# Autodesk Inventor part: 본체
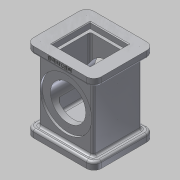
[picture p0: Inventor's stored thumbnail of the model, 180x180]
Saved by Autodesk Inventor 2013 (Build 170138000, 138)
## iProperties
Created: 2017-08
Part Number: 본체
Material: 알루미늄 6061
Document SubType Name: 모델링
Designer: Administrator
Density: 1 g/cm^3
Author: Administrator
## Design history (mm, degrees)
sketch "스케치5"
  geometry: L1 (-939.8, -838.2)-(939.8, -838.2); L2 (939.8, -838.2)-(939.8, 838.2); L3 (939.8, 838.2)-(-939.8, 838.2); L4 (-939.8, 838.2)-(-939.8, -838.2); L5 (-939.8, -838.2)-(939.8, 838.2); L6 (939.8, -838.2)-(-939.8, 838.2); 1 further point
  constraints: 12 end point, 2 midpoint, 2 parallel, 1 horizontal, 1 perpendicular
  dimensions: "d6" = 1879.6 distance of L2.end L3.end; "d8" = 1676.4 distance of L3.end L1.start
extrude "돌출1" new body sketch "스케치5" distance "d9" = 2743.2; taper "d10" = 0 deg
sketch "스케치8"
  geometry: L1 (939.8, -838.2)-(-939.8, -838.2) reference; L2 (939.8, 838.2)-(939.8, -838.2) reference; L3 (-939.8, 838.2)-(939.8, 838.2) reference; L4 (-939.8, -838.2)-(-939.8, 838.2) reference; L5 (-1168.4, -1041.4)-(1168.4, -1041.4); L6 (1168.4, -1041.4)-(1168.4, 1041.4); L7 (1168.4, 1041.4)-(-1168.4, 1041.4); L8 (-1168.4, 1041.4)-(-1168.4, -1041.4); L9 (-1168.4, -1041.4)-(1168.4, 1041.4); L10 (1168.4, -1041.4)-(-1168.4, 1041.4); 1 further point
  constraints: 12 end point, 2 midpoint, 2 parallel, 1 horizontal, 1 perpendicular
  dimensions: "d19" = 2336.8 distance of L6.end L7.end; "d21" = 2082.8 distance of L7.end L5.start
extrude "돌출3" join sketch "스케치8" distance "d22" = 254; taper "d23" = 0 deg
sketch "스케치9"
  geometry: L1 (-609.6, -609.6)-(609.6, -609.6); L2 (609.6, -609.6)-(609.6, 609.6); L3 (609.6, 609.6)-(-609.6, 609.6); L4 (-609.6, 609.6)-(-609.6, -609.6); L5 (-609.6, -609.6)-(609.6, 609.6); L6 (609.6, -609.6)-(-609.6, 609.6); 1 further point
  constraints: 12 end point, 2 midpoint, 2 parallel, 1 horizontal, 1 perpendicular
  dimensions: "d24" = 1219.2 distance of L2.end L3.end; "d26" = 1219.2 distance of L3.end L1.start
extrude "돌출4" cut sketch "스케치9" distance "d27" = 406.4; taper "d28" = 0 deg
sketch "스케치11"
  geometry: L1 (-1168.4, -1041.4)-(1168.4, -1041.4); L2 (1168.4, -1041.4)-(1168.4, 1041.4); L3 (1168.4, 1041.4)-(-1168.4, 1041.4); L4 (-1168.4, 1041.4)-(-1168.4, -1041.4); L5 (-1168.4, -1041.4)-(1168.4, 1041.4); L6 (1168.4, -1041.4)-(-1168.4, 1041.4); 1 further point
  constraints: 12 end point, 2 midpoint, 2 parallel, 1 horizontal, 1 perpendicular
  dimensions: "d34" = 2336.8 distance of L2.end L3.end; "d36" = 2082.8 distance of L3.end L1.start
extrude "돌출6" join sketch "스케치11" distance "d37" = 254; taper "d38" = 0 deg
fillet "모깎기1" dims "d72" = 254
sketch "스케치24"
  geometry: L1 (1854.2, -254)-(25.4, -254) reference; C1 r 889 at (939.8, 1117.6); 2 further points
  constraints: 1 centre point, 1 midpoint, 1 vertical alignment
  dimensions: "d76" = 1371.6 distance from line of L1 C1.centre; "d77" = 1778 diameter of C1
extrude "돌출14" cut sketch "스케치24" distance "d78" = 76.2; taper "d79" = 0 deg
sketch "스케치25"
  geometry: L1 (1854.2, -254)-(25.4, -254) reference; C1 r 889 at (939.8, 1117.6); 2 further points
  constraints: 1 centre point, 1 midpoint, 1 vertical alignment
  dimensions: "d80" = 1371.6 distance from line of L1 C1.centre; "d81" = 1778 diameter of C1
extrude "돌출15" cut sketch "스케치25" distance "d82" = 76.2; taper "d83" = 0 deg
sketch "스케치26"
  geometry: C1 r 889 at (0, 0) reference; C2 r 609.6 at (0, 0); 1 further point
  constraints: 1 centre point, 1 coincident
  dimensions: "d84" = 1219.2 diameter of C2
extrude "돌출16" cut sketch "스케치26" stored distance "d86" = 76.2; taper "d87" = 0 deg
sketch "스케치27"
  geometry: L1 (-660.4, -660.4)-(660.4, -660.4); L2 (660.4, -660.4)-(660.4, 660.4); L3 (660.4, 660.4)-(-660.4, 660.4); L4 (-660.4, 660.4)-(-660.4, -660.4); L5 (-660.4, -660.4)-(660.4, 660.4); L6 (660.4, -660.4)-(-660.4, 660.4); 1 further point
  constraints: 12 end point, 2 midpoint, 2 parallel, 1 horizontal, 1 perpendicular
  dimensions: "d88" = 1320.8 distance of L2.end L3.end; "d91" = 1320.8 distance of L3.end L1.start
extrude "돌출17" cut sketch "스케치27" distance "d92" = 203.2; taper "d93" = 0 deg
sketch "스케치28"
  geometry: L1 (-558.8, 558.8)-(558.8, 558.8); L2 (558.8, 558.8)-(558.8, -558.8); L3 (558.8, -558.8)-(-558.8, -558.8); L4 (-558.8, -558.8)-(-558.8, 558.8); L5 (-558.8, 558.8)-(558.8, -558.8); L6 (558.8, 558.8)-(-558.8, -558.8); 1 further point
  constraints: 12 end point, 2 midpoint, 2 parallel, 1 horizontal, 1 perpendicular
  dimensions: "d94" = 1117.6 distance of L1.start L1.end; "d96" = 1117.6 distance of L3.end L1.start
extrude "돌출18" cut sketch "스케치28" distance "d97" = 1879.6; taper "d98" = 0 deg
fillet "모깎기3" dims "d99" = 76.2
fillet "모깎기5" dims "d101" = 76.2
fillet "모깎기6" dims "d102" = 76.2
sketch "스케치34" dims "d103" = 1473.2
  geometry: C1 r 609.6 at (0, 0) reference; C2 r 889 at (0, 0) reference; 3 further points
  constraints: 2 horizontal alignment, 1 coincident, 2 other
hole "구멍1" sketch "스케치34" at (-736.6, 0) diameter "d105" = 3.4544; stored, may be unused: countersink angle "d109" = 82 deg, drill point angle "d111" = 0 deg; dims "d106" = 101.6, "d107" = 9.525, "d108" = 6.35, "d110" = 152.4
sketch "스케치35" dims "d112" = 1473.2
  geometry: C1 r 609.6 at (0, 0) reference; C2 r 889 at (0, 0) reference; 3 further points
  constraints: 2 vertical alignment, 1 coincident, 2 other
hole "구멍2" sketch "스케치35" at (0, 736.6) diameter "d114" = 3.2512; stored, may be unused: countersink angle "d118" = 82 deg, drill point angle "d120" = 118 deg; dims "d115" = 101.6, "d116" = 9.525, "d117" = 6.35, "d119" = 152.4
chamfer "모따기1" distance "d127" = 25.4; stored, may be unused: second distance "d128" = 3.175, angle "d129" = 45 deg
sketch "스케치36"
  geometry: L1 (-1524, 2082.8)-(0, 2082.8) reference; L2 (0, 0)-(-1524, 0) reference; L3 (-762, 2082.8)-(-762, 0); L4 (25.4, -330.2)-(-1549.4, -330.2) reference; 3 further points
  constraints: 2 end point, 2 midpoint, 2 point on line
  dimensions: "d130" = 965.2 distance from line of L4 point (-762, 635); "d131" = 1066.8 distance of point (-762, 635) point (-762, 1701.8)
hole "구멍3" sketch "스케치36" at (-762, 1701.8), (-762, 635) diameter "d132" = 4.1402; stored, may be unused: countersink angle "d136" = 82 deg, drill point angle "d138" = 118 deg; dims "d133" = 203.2, "d134" = 9.525, "d135" = 6.35, "d137" = 304.8
fillet "모깎기7" dims "d139" = 76.2
sketch "스케치38"
  geometry: A1 r 254 centre (914.4, 787.4) between (1168.4, 787.4) and (914.4, 1041.4) reference; A2 r 254 centre (-914.4, 787.4) between (-914.4, 1041.4) and (-1168.4, 787.4) reference; A3 r 254 centre (-914.4, -787.4) between (-1168.4, -787.4) and (-914.4, -1041.4) reference; A4 r 254 centre (914.4, -787.4) between (914.4, -1041.4) and (1168.4, -787.4) reference; 5 further points
  constraints: 4 coincident
hole "구멍5" sketch "스케치38" at (-914.4, 787.4), (914.4, 787.4), (914.4, -787.4), (-914.4, -787.4) diameter "d147" = 3.2512; stored, may be unused: countersink angle "d151" = 82 deg, drill point angle "d153" = 118 deg; dims "d148" = 101.6, "d149" = 9.525, "d150" = 6.35, "d152" = 152.4
node "작업 평면2"
sketch "스케치39"
  geometry: L1 (492.974, -15.199)-(1335.826, -15.199); L2 (1335.826, -15.199)-(1335.826, -137.201); L3 (1335.826, -137.201)-(492.974, -137.201); L4 (492.974, -137.201)-(492.974, -15.199); L5 (492.974, -76.2)-(1335.826, -76.2); L6 (914.4, -15.199)-(914.4, -137.201); L7 (1828.8, -177.8)-(0, -177.8) reference; L8 (0, -254)-(1828.8, -254) reference; L9 (-254, -177.8)-(0, -177.8) reference; L10 (-254, 0)-(-254, -177.8) reference; 1 further point
  constraints: 4 end point, 4 midpoint, 2 other
  dimensions: "d158" = 1168.4 distance between parallel lines of L10 L6; "d159" = 101.6 distance between parallel lines of L9 L5
extrude "돌출19" join sketch "스케치39" stored distance "d160" = 1879.6; taper "d161" = 0 deg
sketch "스케치40"
  geometry: A1 r 254 centre (-914.4, -787.4) between (-1168.4, -787.4) and (-914.4, -1041.4) reference; A2 r 254 centre (914.4, -787.4) between (914.4, -1041.4) and (1168.4, -787.4) reference; A3 r 254 centre (914.4, 787.4) between (1168.4, 787.4) and (914.4, 1041.4) reference; A4 r 254 centre (-914.4, 787.4) between (-914.4, 1041.4) and (-1168.4, 787.4) reference; 5 further points
  constraints: 4 coincident
hole "구멍6" sketch "스케치40" at (-914.4, 787.4), (914.4, 787.4), (914.4, -787.4), (-914.4, -787.4) diameter "d162" = 3.2512; stored, may be unused: countersink angle "d166" = 82 deg, drill point angle "d168" = 118 deg; dims "d163" = 101.6, "d164" = 9.525, "d165" = 6.35, "d167" = 152.4
node "솔리드1"
pattern_circular "원형 패턴1" dims angle "d122" = 360 deg
pattern_circular "원형 패턴2" dims angle "d125" = 360 deg
other parameters: "K계수" = 4.4, "BendRadius" = 3.048 (derived), "BendReliefWidth" = 3.048 (derived), "BendReliefDepth" = 1.524 (derived), "CornerReliefSize" = 12.192 (derived), "SeamGap" = 0.00508, "MinimumRemnant" = 6.096 (derived), "TransitionRadius" = 3.048 (= BendRadius), "d154" = 12.7
